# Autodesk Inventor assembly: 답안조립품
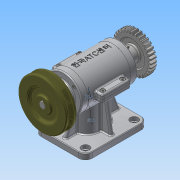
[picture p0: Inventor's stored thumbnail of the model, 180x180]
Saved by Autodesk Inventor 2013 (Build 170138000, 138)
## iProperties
Created: 2015-09
Part Number: 답안조립품
Document SubType Name: Assembly
Designer: Administrator
Author: Administrator
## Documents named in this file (17)
- C:\Users\Administrator\Desktop\350908v1016\답안조립품.iam
- C:\Users\Administrator\Desktop\350908v1016\본체.ipt
- C:\Users\Administrator\Desktop\350908v1016\본체 커버.ipt
- C:\Users\Administrator\Desktop\350908v1016\편심축.ipt
- C:\Users\Administrator\Desktop\350908v1016\앞커버.ipt
- C:\Users\Administrator\Desktop\350908v1016\뒤커버.ipt
- C:\Users\Administrator\Desktop\350908v1016\V-벨트풀리.ipt
- C:\Users\Administrator\Desktop\350908v1016\키4x4.ipt
- C:\Users\Administrator\Desktop\350908v1016\스퍼기어.ipt
- C:\Users\Administrator\Desktop\350908v1016\오일실.ipt
- C:\Users\Administrator\Desktop\350908v1016\멈춤나사.ipt
- C:\Users\Administrator\Desktop\350908v1016\M3x0.5x8.ipt
- C:\Users\Administrator\Desktop\350908v1016\베어링 6202.ipt
- C:\Users\Administrator\Desktop\350908v1016\베어링 6201.ipt
- C:\Users\Administrator\Desktop\350908v1016\슬라이드.ipt
- C:\Users\Administrator\Desktop\350908v1016\스프링.ipt
- C:\Users\Administrator\Desktop\350908v1016\M4x0.5x14.ipt
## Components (13 placed, 3 different names)
1. V-벨트풀리:1 — 플러쉬:1
2. M4x0.5x14:1
3. M4x0.5x14:2
4. M4x0.5x14:3
5. M4x0.5x14:4
6. M3x0.5x8:2
7. M3x0.5x8:3
8. M3x0.5x8:4
9. M3x0.5x8:5
10. M3x0.5x8:1
11. M3x0.5x8:6
12. M3x0.5x8:7
13. M3x0.5x8:8
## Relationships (1: Flush 1)
- 플러쉬:1 [Flush]: V-벨트풀리:1
